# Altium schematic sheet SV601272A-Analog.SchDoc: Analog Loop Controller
size 431 x 279 mm; Date: Not shown in title block; ApprovedBy: Not shown in title block; CheckedBy: Not shown in title block; Author: Not shown in title block; CompanyName: Not shown in title block; Engineer: Not shown in title block; Organization: Not shown in title block; Address1: Not shown in title block; Address2: Not shown in title block; Address3: Not shown in title block; Address4: Not shown in title block; DocumentNumber: 7; Revision: Use project parameter SCH_Rev; SheetNumber: 7; SheetTotal: 11; PageSetup: Record=PageOptions¦CenterHorizontal=True¦CenterVertical=True¦PrintScale=1.00¦XCorrection=1.00¦YCorrection=1.00¦PrintKind=0¦BorderSize=5000000¦LeftOffset=0¦BottomOffset=0¦Orientation=2¦PaperLength=1000¦PaperWidth=1000¦Scale=100¦PaperSource=15¦PrintQuality=600¦MediaType=1¦DitherType=10¦PaperKind=Letter¦PrintScaleMode=1
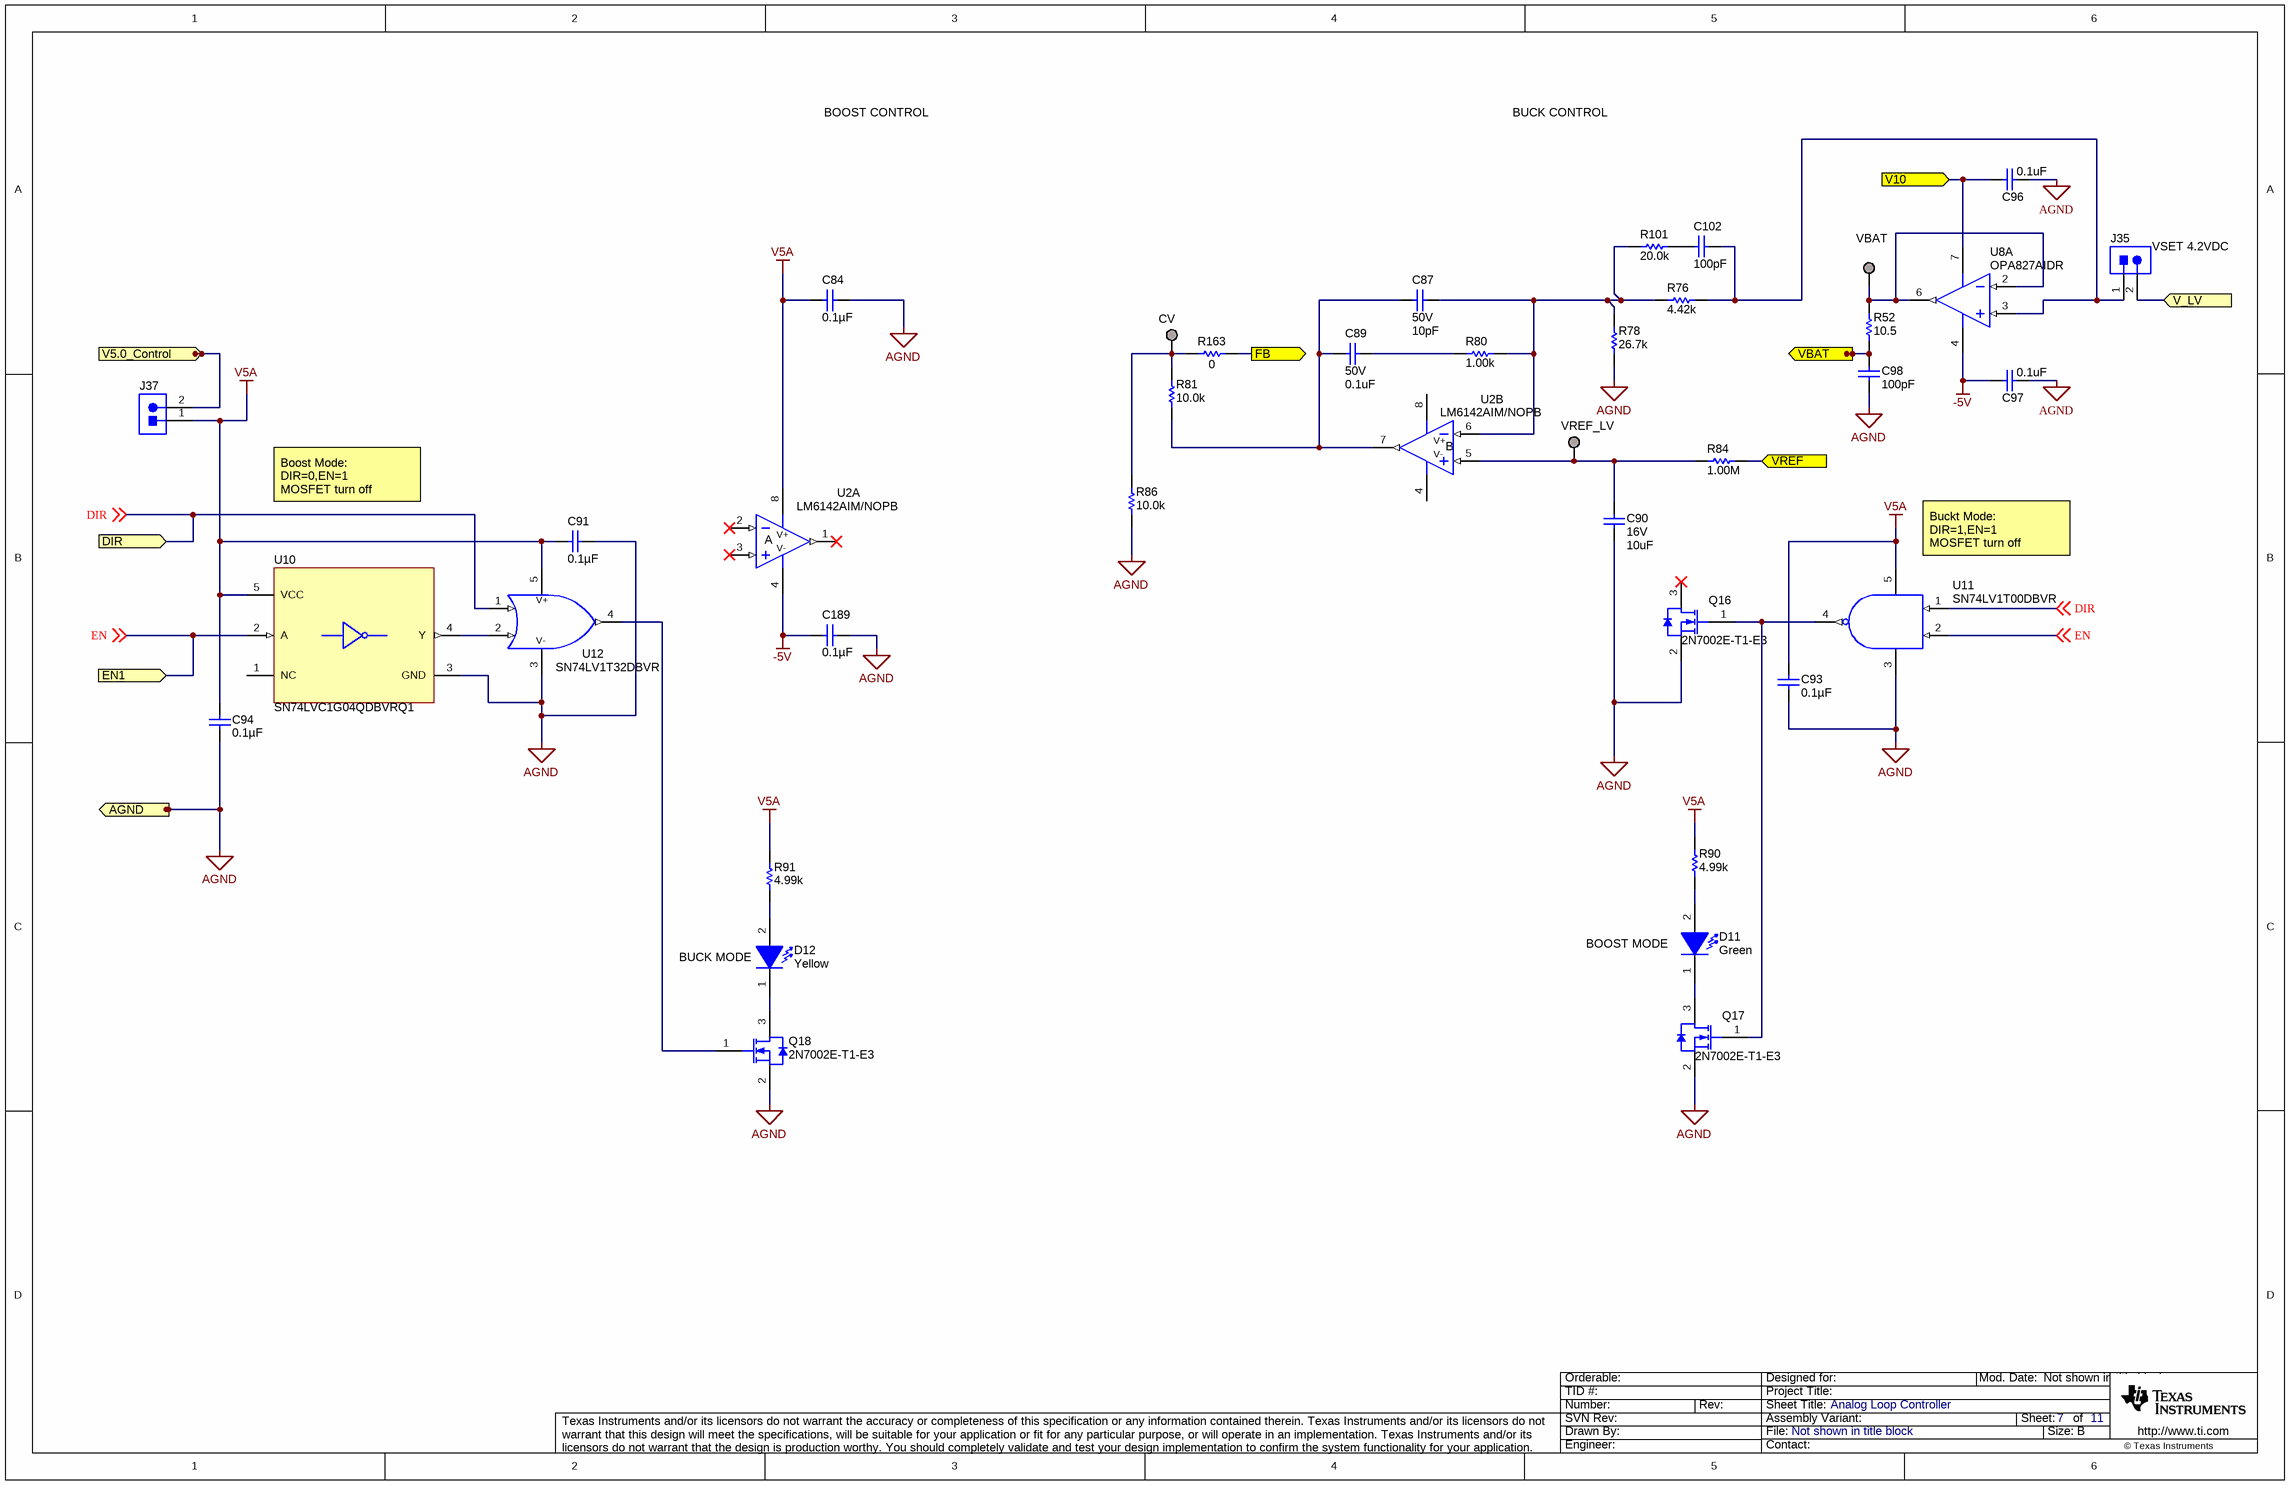
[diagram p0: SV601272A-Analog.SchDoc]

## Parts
C84  ValueDisplayed: 0.1µF  [0603L]  (hidden comment: GRM188R72A104KA35D)
C87  VDC_V: 50V  ValueDisplayed: 10pF  [0603]  (hidden comment: C0603C100J5GACTU)
C89  VDC_V: 50V  ValueDisplayed: 0.1uF  [0603]  (hidden comment: C1608X5R1H104K080AA)
C90  VDC_V: 16V  ValueDisplayed: 10uF  [0603]  (hidden comment: EMK107BBJ106MA-T)
C91  ValueDisplayed: 0.1µF  [0603L]  (hidden comment: GRM188R72A104KA35D)
C93  ValueDisplayed: 0.1µF  [0603L]  (hidden comment: GRM188R72A104KA35D)
C94  ValueDisplayed: 0.1µF  [0603L]  (hidden comment: GRM188R72A104KA35D)
C96  ValueDisplayed: 0.1uF  [0603]  (hidden comment: Capacitor)
C97  ValueDisplayed: 0.1uF  [0603]  (hidden comment: Capacitor)
C98  ValueDisplayed: 100pF  [0603L]  (hidden comment: Capacitor)
C102  ValueDisplayed: 100pF  [0603L]  (hidden comment: C0603C101J5GACTU)
C189  ValueDisplayed: 0.1µF  [0603L]  (hidden comment: GRM188R72A104KA35D)
CV  Pogo Pad  [PogoPad]  (value not drawn)  (no BOM)
D11  value Green  [WL-SMCW_GREEN]  (hidden comment: 150060VS75000)
D12  value Yellow  [WL-SMCW_YELLOW]  (hidden comment: 150060YS75000)
J35  HTSW-102-07-G-S  [Samtec_HTSW-102-07-G-S]  (value not drawn)
J37  HTSW-102-07-G-S  [Samtec_HTSW-102-07-G-S]  (value not drawn)
Q16  2N7002E-T1-E3  [SOT-23]
Q17  2N7002E-T1-E3  [SOT-23]
Q18  2N7002E-T1-E3  [SOT-23]
R52  ValueDisplayed: 10.5  [0603]  (hidden comment: RC0603FR-0710R5L)
R76  ValueDisplayed: 4.42k  [0603L]  (hidden comment: CRCW06034K42FKEA)
R78  ValueDisplayed: 26.7k  [0603L]  (hidden comment: CRCW060326K7FKEA)
R80  ValueDisplayed: 1.00k  [0603]  (hidden comment: CRCW06031K00FKEA)
R81  ValueDisplayed: 10.0k  [0603L]  (hidden comment: CRCW060310K0FKEA)
R84  ValueDisplayed: 1.00M  [0603]  (hidden comment: MCT06030C1004FP500)
R86  ValueDisplayed: 10.0k  [0603L]  (hidden comment: CRCW060310K0FKEA)
R90  ValueDisplayed: 4.99k  [0603L]  (hidden comment: CRCW06034K99FKEA)
R91  ValueDisplayed: 4.99k  [0603L]  (hidden comment: CRCW06034K99FKEA)
R101  ValueDisplayed: 20.0k  [0603L]  (hidden comment: CRCW060320K0FKEA)
R163  ValueDisplayed: 0  [0603]  (hidden comment: Resistor)
U2  LM6142AIM/NOPB  [D0008A_N]  (parts A,B of 2)
U8  OPA827AIDR  [D0008A_L]  (part A of 2)
U10  SN74LVC1G04QDBVRQ1  [DBV0005A_N]
U11  SN74LV1T00DBVR  [DBV0005A_N]
U12  SN74LV1T32DBVR  [DBV0005A_N]
VBAT  Pogo Pad  [PogoPad]  (value not drawn)  (no BOM)
VREF_LV  Pogo Pad  [PogoPad]  (value not drawn)  (no BOM)

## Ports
AGND, DIR, EN1, FB, V5.0_Control, V10, V_LV, VBAT, VREF

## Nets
-5V: C97.1 C189.1 U2.4(V-) U8.4(V-)
AGND: C84.2 C90.2 C91.1 C93.2 C94.1 C96.2 C97.2 C98.2 C189.2 Q16.2(S) Q17.2(S) Q18.2(S) R78.1 R86.2 U10.3(GND) U11.3(GND) U12.3(GND) ; port AGND
V5A: C84.1 C91.2 C93.1 C94.2 J37.1 R90.1 R91.1 U2.8(V+) U10.5(VCC) U11.5(VCC) U12.5(VCC)
DIR: U11.1(A) U12.1(A) ; off-sheet DIR, port DIR
EN: U10.2(A) U11.2(B) ; off-sheet EN, port EN1
FB: R163.2 ; port FB
V5.0_Control: J37.2 ; port V5.0_Control
V10: C96.1 U8.7(V+) ; port V10
V_LV: J35.2 ; port V_LV
VBAT: C98.1 R52.1 ; port VBAT
VREF: R84.2 ; port VREF
NetC87_1: C87.1 R76.2 R78.2 R80.2 R101.2 U2.6(IN-)
NetC87_2: C87.2 C89.2 R81.2 U2.7(OUT)
NetC89_1: C89.1 R80.1
NetC90_1: C90.1 R84.1 U2.5(IN+) VREF_LV.1
NetC102_1: C102.1 J35.1 R76.1 U8.3(IN+)
NetC102_2: C102.2 R101.1
NetCV_1: CV.1 R81.1 R86.1 R163.1
NetD11_1: D11.1(K) Q17.3(D)
NetD11_2: D11.2(A) R90.2
NetD12_1: D12.1(K) Q18.3(D)
NetD12_2: D12.2(A) R91.2
NetQ16_1: Q16.1(G) Q17.1(G) U11.4(Y)
NetQ18_1: Q18.1(G) U12.4(Y)
NetR52_2: R52.2 U8.2(IN-) U8.6(OUT) VBAT.1
NetU10_4: U10.4(Y) U12.2(B)

Not connected (* = marked no-connect by the designer): Q16 3(D)*; U2 1(OUT)* 2(IN-)* 3(IN+)*; U10 1(NC)

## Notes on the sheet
- BOOST CONTROL
- BUCK CONTROL
- (near J35) VSET 4.2VDC
- Boost Mode: DIR=0,EN=1
  MOSFET turn off
- (near U11) Buckt Mode: DIR=1,EN=1
  MOSFET turn off
- (near D12) BUCK MODE
- (near D11) BOOST MODE

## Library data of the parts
C84 C91 C93 C94 C189 = GRM188R72A104KA35D: CAP, CERM, 0.1 µF, 100 V, +/- 10%, X7R, 0603; Manufacturer: MuRata; Polarized: N; CompType: Capacitor; Value: 0.1uF; U/M: EA; Cap_F: 0.0000001; Tolerance_%: 10; Value1: Unknown; VDC_V: 100; Value2: 100V; TaMin_C: -55; TaMax_C: 125; Cap_Case: 0603; AEC Category: Q200
C87 = CMP-0006839-4: CAP, CERM, 10 pF, 50 V, +/- 5%, C0G/NP0, 0603; Manufacturer: Kemet; TaMin_C: -55°C; Polarized: N; SizeAreaWB_mm2: 4.68; Value1: Unknown; U/M: EA; Value: 10pF; TaMax_C: 125°C; SizeZ_mm: 1; SizeX_mm: 1.6; SizeY_mm: 0.8; SizeArea_mm2: 1.28; CompType: Capacitor; AEC Category: Q200
C89 = CMP-0007010-5: CAP, CERM, 0.1 uF, 50 V, +/- 10%, X5R, 0603; Manufacturer: TDK; TaMin_C: -55°C; ESR_ohm: 0.0296; Polarized: N; SizeAreaWB_mm2: 4.68; Value1: 0.0296 ohm; U/M: EA; Value: 0.1uF; TaMax_C: 85°C; SizeZ_mm: 1; SizeX_mm: 1.6; SizeY_mm: 0.8; SizeArea_mm2: 1.28; CompType: Capacitor; Cap_F: 100nF; IRMS_A: 9.7199dA; AEC Category: Q200
C90 = CMP-0007122-5: CAP, CERM, 10 uF, 16 V, +/- 20%, X5R, 0603; Manufacturer: Taiyo Yuden; TaMin_C: -55°C; Polarized: N; SizeAreaWB_mm2: 4.68; Value1: Unknown; U/M: EA; Value: 10uF; TaMax_C: 85°C; SizeZ_mm: 1; SizeX_mm: 1.6; SizeY_mm: 0.8; SizeArea_mm2: 1.28; CompType: Capacitor; Cap_F: 10µF; AEC Category: Q200
C96 C97 = CMP-0006752-5: CAP, CERM, 0.1 uF, 25 V, +/- 5%, X7R, 0603; PartNumber: 06033C104JAT2A; Manufacturer: AVX; Polarized: N; Value: 0.1uF; U/M: EA; Cap_F: 100nF; ESR_ohm: 0.05; Value1: 0.05 ohm; VDC_V: 25V; TaMin_C: -55°C; TaMax_C: 125°C; AEC Category: Q200; SizeArea_mm2: 1.28; SizeAreaWB_mm2: 4.68; SizeX_mm: 1.6; SizeY_mm: 0.8; SizeZ_mm: 1
C98 = CMP-0006841-4: CAP, CERM, 100 pF, 50 V, +/- 5%, C0G/NP0, 0603; PartNumber: C0603C101J5GACTU; Manufacturer: Kemet; Polarized: N; Value: 100pF; U/M: EA; Value1: Unknown; VDC_V: 50V; TaMin_C: -55°C; TaMax_C: 125°C; Cap_Case: 0603; AEC Category: Q200; SizeArea_mm2: 1.28; SizeAreaWB_mm2: 4.68; SizeX_mm: 1.6; SizeY_mm: 0.8; SizeZ_mm: 1
C102 = C0603C101J5GACTU: CAP, CERM, 100 pF, 50 V, +/- 5%, C0G/NP0, 0603; Manufacturer: Kemet; Polarized: N; CompType: Capacitor; Value: 100pF; U/M: EA; Cap_F: 0.0000000001; Tolerance_%: 5; Value1: Unknown; VDC_V: 50; Value2: 50V; TaMin_C: -55; TaMax_C: 125; Cap_Case: 0603
CV VBAT VREF_LV = PogoPad: Pad for Pogo Pin Connector; SymbolCreator: codlsc
D11 = 150060VS75000: LED, Green, SMD; Manufacturer: Wurth Elektronik; Type: AlInGaP; Vf_V: 2; Value2: 2V; Io_A: 0.02; Value1: W; U/M: EA
D12 = 150060YS75000: LED, Yellow, SMD; Manufacturer: Wurth Elektronik; Type: AlInGaP; Vf_V: 2; Value2: 2V; Io_A: 0.02; Value1: W; U/M: EA
J35 J37 = HTSW-102-07-G-S: Header, 100mil, 2x1, Gold, TH; Manufacturer: Samtec; SymbolCreator: a0412235; U/M: EA
Q16-Q18 = 2N7002E-T1-E3: MOSFET, N-CH, 60 V, 0.24 A, SOT-23; Manufacturer: Vishay-Siliconix; Alternate Manufacturer: None; U/M: EA; ChType: N; Value: 60V; VdsMax_V: 60; Value1: 1.8 ohm; Rdson45_ohm: 1.8; Value2: 0.4 nC; QgTyp_nC: 0.4; Vgs_V: 20; IdsMax_A: 0.24
R52 = CMP-0022749-2: RES, 10.5, 1%, 0.1 W, 0603; Manufacturer: Yageo America; Power_W: 100mW; TempCo: 200 ppm/C; Value_Code: 10R5; U/M: EA; Value: 10.5; EIA_Code: E96; SizeX_mm: 1.6; SizeY_mm: 0.8; SizeZ_mm: 1; Value2: 0.1W; SizeArea_mm2: 1.28; CompType: Resistor; VDC_V: 150V; AEC Category: Q200
R76 = CRCW06034K42FKEA: RES, 4.42 k, 1%, 0.1 W, 0603; Manufacturer: Vishay-Dale; CompType: Resistor; Value: 4.42k; Res_ohm: 4420; Value_Code: 4k42; Tolerance_%: 1; Power_W: 0.1; Value2: 0.1W; VDC_V: 75; TempCo: 100 ppm/C; EIA_Code: E96; U/M: EA; AEC Category: Q200; SizeArea_mm2: 1.28; SizeX_mm: 1.6; SizeY_mm: 0.8
R78 = CRCW060326K7FKEA: RES, 26.7 k, 1%, 0.1 W, 0603; Manufacturer: Vishay-Dale; CompType: Resistor; Value: 26.7k; Res_ohm: 26700; Value_Code: 26k7; Tolerance_%: 1; Power_W: 0.1; Value2: 0.1W; VDC_V: 75; TempCo: 100 ppm/C; EIA_Code: E96; U/M: EA; AEC Category: Q200; SizeArea_mm2: 1.28; SizeX_mm: 1.6; SizeY_mm: 0.8
R80 = CMP-0022109-5: RES, 1.00 k, 1%, 0.1 W, AEC-Q200 Grade 0, 0603; Manufacturer: Vishay-Dale; Power_W: 100mW; TempCo: 100 ppm/C; Value_Code: 1k00; Value: 1.00k; EIA_Code: E96; Res_ohm: 1k; SizeX_mm: 1.6; SizeY_mm: 0.8; SizeZ_mm: 1; Value2: 0.1W; SizeArea_mm2: 1.28; CompType: Resistor; AEC Qualified: Y; VDC_V: 75V; AEC Category: Q200; AEC Grade: 0
R81 R86 = CRCW060310K0FKEA: RES, 10.0 k, 1%, 0.1 W, 0603; Manufacturer: Vishay-Dale; CompType: Resistor; Value: 10.0k; Res_ohm: 10000; Value_Code: 10k0; Tolerance_%: 1; Power_W: 0.1; Value2: 0.1W; VDC_V: 75; TempCo: 100 ppm/C; EIA_Code: E96; U/M: EA
R84 = CMP-0022731-2: RES, 1.00 M, 1%, 0.125 W, 0603; Manufacturer: Vishay/Beyschlag; Power_W: 125mW; TempCo: 50 ppm/C; Value_Code: 1M00; U/M: EA; Value: 1.00Meg; EIA_Code: E96; Res_ohm: 1M; SizeX_mm: 1.6; SizeY_mm: 0.8; SizeZ_mm: 1; Value2: 0.125W; SizeArea_mm2: 1.28; CompType: Resistor; AEC Qualified: N; VDC_V: 75V; AEC Category: Q200
R90 R91 = CRCW06034K99FKEA: RES, 4.99 k, 1%, 0.1 W, 0603; Manufacturer: Vishay-Dale; CompType: Resistor; Value: 4.99k; Res_ohm: 4990; Value_Code: 4k99; Tolerance_%: 1; Power_W: 0.1; Value2: 0.1W; VDC_V: 75; TempCo: 100 ppm/C; EIA_Code: E96; U/M: EA
R101 = CRCW060320K0FKEA: RES, 20.0 k, 1%, 0.1 W, 0603; Manufacturer: Vishay-Dale; CompType: Resistor; Value: 20.0k; Res_ohm: 20000; Value_Code: 20k0; Tolerance_%: 1; Power_W: 0.1; Value2: 0.1W; VDC_V: 75; TempCo: 100 ppm/C; EIA_Code: E96; U/M: EA; SizeArea_mm2: 1.28; SizeX_mm: 1.6; SizeY_mm: 0.8; AEC Category: Q200
R163 = CMP-0025874-3: RES, 0, 5%, 0.1 W, 0603; PartNumber: ERJ-3GEY0R00V; Manufacturer: Panasonic; Value: 0; Value_Code: 0000; Power_W: 100mW; Value2: 0.1W; VDC_V: 50V; TempCo: 600 ppm/C; EIA_Code: E24; U/M: EA; AEC Category: Q200; SizeArea_mm2: 1.28; SizeX_mm: 1.6; SizeY_mm: 0.8; SizeZ_mm: 1
U2 = LM6142AIM: 17MHz Rail-to-Rail Input and Output Op Amp, D0008A; Manufacturer: Texas Instruments; CompType: OpAmp IC
U8 = CMP-0041267-2: Low-Noise, High-Precision, JFET-Input Operational Amplifier, 8 to 36 V, -40 to 125 degC, 8-pin SOIC (D8), Green (RoHS & no Sb/Br); Manufacturer: Texas Instruments; Vmax(V): 36; GBW(Typ)(MHz): 22; Vmin(V): 8; Iq per channel(Max)(mA): 5.2; SubFamily: Audio Operational Amplifier; Number of Channels: 1; Vn at Flatband(Typ)(nV/rtHz): 4
U10 = SN74LVC1G04QDBVRQ1: Single Inverter Gate, DBV0005A; Manufacturer: Texas Instruments; SymbolCreator: a0411947; CompType: IC; U/M: EA
U11 = SN74LV1T00DBVR: Single Power Supply 2-Input Positive NAND Gate CMOS Logic Level Shifter, DBV0005A; Manufacturer: Texas Instruments; SymbolCreator: a0411947; CompType: IC; U/M: EA
U12 = SN74LV1T32DBVR: Single Power Supply 2-Input Positive OR Gate CMOS Logic Level Shifter, DBV0005A; Manufacturer: Texas Instruments; SymbolCreator: a0411947; CompType: IC; U/M: EA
